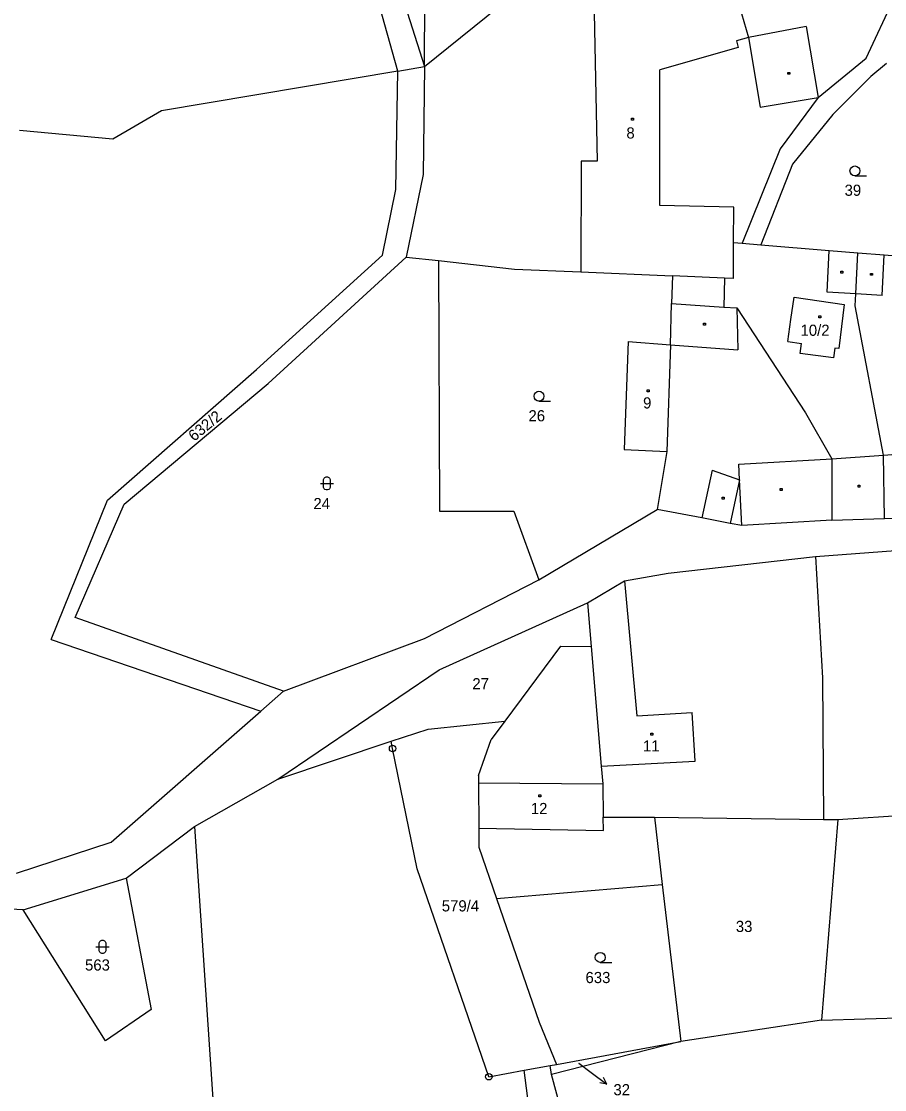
# Model space of a CAD drawing. Extents: x -794421 to -792735, y -1117671 to -1115559.
# Drawn here: x -793541.7 to -793410.2, y -1117055.3 to -1116892.5 of the extents above; entities that cross this region are included whole.
import ezdxf

# ---------------------------------------------------------------- set-up
doc = ezdxf.new("R2010")
doc.units = 0
for name, color, linetype in [('Komunikace', 7, 'Continuous'), ('Vrstva 1', 7, 'Continuous'), ('Vrstva 14', 7, 'Continuous'), ('Vrstva 15', 7, 'Continuous'), ('Vrstva 16', 7, 'Continuous'), ('Vrstva 2', 7, 'Continuous'), ('Vrstva 23', 7, 'Continuous'), ('Vrstva 25', 7, 'Continuous'), ('Vrstva 28', 7, 'Continuous')]:
    doc.layers.add(name, color=color, linetype=linetype)

msp = doc.modelspace()

# ---------------------------------------------------------------- linework, layer by layer
at = {"layer": 'Komunikace'}
msp.add_line((-793456.75, -1117051.29), (-793454.9, -1117052.67), dxfattribs=at)
at = {"layer": 'Vrstva 1'}
for p, q in [((-793484.35, -1116900.11), (-793495.76, -1116859.33)), ((-793493.13, -1116859), (-793480.31, -1116899.44)), ((-793412.98, -1116898.15), (-793406.34, -1116883.78)), ((-793433.75, -1116885.1), (-793430.93, -1116895.01)), ((-793480.31, -1116899.44), (-793464.48, -1116886.66)), ((-793480.31, -1116899.44), (-793480.23, -1116887.15)), ((-793454.44, -1116891.23), (-793454, -1116913.82)), ((-793422.11, -1116893.31), (-793430.93, -1116895.01)), ((-793422.11, -1116893.31), (-793420.28, -1116904.12)), ((-793420.28, -1116904.12), (-793412.98, -1116898.15)), ((-793484.35, -1116900.11), (-793520.39, -1116906.15)), ((-793484.67, -1116918.16), (-793484.35, -1116900.11)), ((-793484.35, -1116900.11), (-793480.31, -1116899.44)), ((-793480.31, -1116899.44), (-793480.48, -1116915.89)), ((-793409.89, -1116898.96), (-793412.29, -1116900.96)), ((-793412.29, -1116900.96), (-793418.05, -1116906.75)), ((-793420.28, -1116904.12), (-793426.11, -1116911.97)), ((-793520.39, -1116906.15), (-793527.81, -1116910.47)), ((-793418.05, -1116906.75), (-793424.23, -1116914.28)), ((-793527.81, -1116910.47), (-793542.02, -1116909.19)), ((-793426.11, -1116911.97), (-793431.88, -1116926.34)), ((-793456.41, -1116913.84), (-793456.46, -1116930.7)), ((-793454, -1116913.82), (-793456.41, -1116913.84)), ((-793424.23, -1116914.28), (-793429.04, -1116926.58)), ((-793480.48, -1116915.89), (-793483.08, -1116928.45)), ((-793486.7, -1116928.15), (-793484.67, -1116918.16)), ((-793433.23, -1116931.71), (-793433.2, -1116926.23)), ((-793433.2, -1116926.23), (-793431.88, -1116926.34)), ((-793431.88, -1116926.34), (-793429.04, -1116926.58)), ((-793429.04, -1116926.58), (-793418.62, -1116927.44)), ((-793418.62, -1116927.44), (-793414.25, -1116927.8)), ((-793414.56, -1116934.07), (-793414.25, -1116927.8)), ((-793414.25, -1116927.8), (-793410.24, -1116928.13)), ((-793505.9, -1116945.6), (-793486.7, -1116928.15)), ((-793504.14, -1116947.69), (-793483.08, -1116928.45)), ((-793483.08, -1116928.45), (-793478.18, -1116928.99)), ((-793478.18, -1116928.99), (-793478.01, -1116967.17)), ((-793478.18, -1116928.99), (-793466.59, -1116930.28)), ((-793410.24, -1116928.13), (-793404, -1116928.64)), ((-793466.59, -1116930.28), (-793456.46, -1116930.7)), ((-793456.46, -1116930.7), (-793442.51, -1116931.29)), ((-793442.51, -1116931.29), (-793442.63, -1116935.51)), ((-793434.57, -1116931.65), (-793442.51, -1116931.29)), ((-793434.57, -1116931.65), (-793434.69, -1116936.06)), ((-793433.23, -1116931.71), (-793434.57, -1116931.65)), ((-793414.65, -1116935.87), (-793414.56, -1116934.07)), ((-793442.82, -1116941.81), (-793442.63, -1116935.51)), ((-793434.69, -1116936.06), (-793432.71, -1116936.2)), ((-793410.35, -1116958.65), (-793414.65, -1116935.87)), ((-793432.71, -1116936.2), (-793422.24, -1116952.16)), ((-793449.26, -1116941.34), (-793449.88, -1116957.77)), ((-793449.26, -1116941.34), (-793442.82, -1116941.81)), ((-793528.62, -1116965.47), (-793505.9, -1116945.6)), ((-793526.04, -1116966.12), (-793504.14, -1116947.69)), ((-793422.24, -1116952.16), (-793418.23, -1116959.21)), ((-793449.88, -1116957.77), (-793443.37, -1116958.06)), ((-793443.37, -1116958.06), (-793444.86, -1116966.92)), ((-793410.19, -1116968.29), (-793410.35, -1116958.65)), ((-793418.23, -1116959.21), (-793418.24, -1116968.53)), ((-793537.18, -1116986.72), (-793528.62, -1116965.47)), ((-793533.55, -1116983.36), (-793526.04, -1116966.12)), ((-793462.86, -1116977.65), (-793444.86, -1116966.92)), ((-793438.02, -1116968.2), (-793444.86, -1116966.92)), ((-793478.01, -1116967.17), (-793466.67, -1116967.15)), ((-793466.67, -1116967.15), (-793462.86, -1116977.65)), ((-793433.69, -1116969.02), (-793438.02, -1116968.2)), ((-793418.24, -1116968.53), (-793431.92, -1116969.35)), ((-793418.24, -1116968.53), (-793410.19, -1116968.29)), ((-793410.19, -1116968.29), (-793402.09, -1116967.98)), ((-793431.92, -1116969.35), (-793433.69, -1116969.02)), ((-793420.73, -1116974.09), (-793391.73, -1116971.89)), ((-793443.14, -1116976.59), (-793420.73, -1116974.09)), ((-793420.73, -1116974.09), (-793419.65, -1116992.58)), ((-793449.81, -1116977.8), (-793443.14, -1116976.59)), ((-793480.3, -1116986.56), (-793462.86, -1116977.65)), ((-793455.46, -1116981.14), (-793449.81, -1116977.8)), ((-793478.04, -1116991.32), (-793455.46, -1116981.14)), ((-793455.46, -1116981.14), (-793454.9, -1116987.78)), ((-793501.76, -1116994.58), (-793533.55, -1116983.36)), ((-793501.76, -1116994.58), (-793480.3, -1116986.56)), ((-793537.18, -1116986.72), (-793505.25, -1116997.64)), ((-793459.56, -1116987.73), (-793468.07, -1116999.16)), ((-793459.56, -1116987.73), (-793454.9, -1116987.78)), ((-793454.9, -1116987.78), (-793453.36, -1117006.02)), ((-793502.66, -1117008.02), (-793478.04, -1116991.32)), ((-793419.65, -1116992.58), (-793419.5, -1117014.13)), ((-793505.25, -1116997.64), (-793501.76, -1116994.58)), ((-793528.06, -1117017.62), (-793505.25, -1116997.64)), ((-793479.72, -1117000.39), (-793468.07, -1116999.16)), ((-793468.07, -1116999.16), (-793470.15, -1117001.95)), ((-793485.38, -1117002.2), (-793479.72, -1117000.39)), ((-793502.66, -1117008.02), (-793485.38, -1117002.2)), ((-793485.15, -1117003.33), (-793485.38, -1117002.2)), ((-793472.08, -1117007.46), (-793470.15, -1117001.95)), ((-793481.39, -1117021.68), (-793485.15, -1117003.33)), ((-793453.36, -1117006.02), (-793453.13, -1117008.72)), ((-793472.08, -1117007.46), (-793472.08, -1117008.58)), ((-793515.34, -1117015.21), (-793502.66, -1117008.02)), ((-793472.08, -1117008.58), (-793472.03, -1117015.46)), ((-793453.13, -1117008.72), (-793453.06, -1117013.8)), ((-793417.29, -1117014.16), (-793391.93, -1117012.5)), ((-793453.06, -1117013.8), (-793445.23, -1117013.81)), ((-793445.23, -1117013.81), (-793444.1, -1117024.06)), ((-793445.23, -1117013.81), (-793419.5, -1117014.13)), ((-793417.29, -1117014.16), (-793419.8, -1117044.7)), ((-793419.5, -1117014.13), (-793417.29, -1117014.16)), ((-793525.73, -1117023.07), (-793515.34, -1117015.21)), ((-793515.34, -1117015.21), (-793508.73, -1117114.25)), ((-793472.03, -1117015.46), (-793472.01, -1117018.35)), ((-793542.45, -1117022.32), (-793528.06, -1117017.62)), ((-793472.01, -1117018.35), (-793469.31, -1117026.18)), ((-793470.5, -1117053.33), (-793481.39, -1117021.68)), ((-793541.43, -1117027.89), (-793525.73, -1117023.07)), ((-793525.73, -1117023.07), (-793521.97, -1117043.07)), ((-793469.31, -1117026.18), (-793444.1, -1117024.06)), ((-793444.1, -1117024.06), (-793441.22, -1117047.99)), ((-793541.43, -1117027.89), (-793556.14, -1117027.18)), ((-793469.31, -1117026.18), (-793462.81, -1117045.04)), ((-793528.89, -1117047.89), (-793541.43, -1117027.89)), ((-793521.97, -1117043.07), (-793528.89, -1117047.89)), ((-793462.81, -1117045.04), (-793460.19, -1117051.45)), ((-793419.8, -1117044.7), (-793441.22, -1117047.99)), ((-793419.8, -1117044.7), (-793387.04, -1117043.8)), ((-793441.22, -1117047.99), (-793460.94, -1117053)), ((-793460.19, -1117051.45), (-793441.22, -1117047.99)), ((-793465.13, -1117052.35), (-793461.14, -1117051.62)), ((-793461.14, -1117051.62), (-793460.19, -1117051.45)), ((-793460.94, -1117053), (-793461.14, -1117051.62)), ((-793470.5, -1117053.33), (-793465.13, -1117052.35)), ((-793463.93, -1117061.05), (-793465.13, -1117052.35)), ((-793451.13, -1117089.23), (-793460.94, -1117053))]:
    msp.add_line(p, q, dxfattribs=at)
at = {"layer": 'Vrstva 16'}
for p, q in [((-793454.9, -1117052.67), (-793452.495, -1117054.463)), ((-793452.495, -1117054.463), (-793453.595, -1117054.266)), ((-793452.495, -1117054.463), (-793452.997, -1117053.464))]:
    msp.add_line(p, q, dxfattribs=at)
at = {"layer": 'Vrstva 2'}
for p, q in [((-793430.93, -1116895.01), (-793432.77, -1116895.53)), ((-793430.93, -1116895.01), (-793429.12, -1116905.6)), ((-793432.49, -1116896.52), (-793444.45, -1116899.92)), ((-793432.77, -1116895.53), (-793432.49, -1116896.52)), ((-793444.45, -1116920.58), (-793444.45, -1116899.92)), ((-793429.12, -1116905.6), (-793420.28, -1116904.12)), ((-793433.18, -1116920.85), (-793444.45, -1116920.58)), ((-793433.2, -1116926.23), (-793433.18, -1116920.85)), ((-793418.94, -1116933.8), (-793418.62, -1116927.44)), ((-793410.54, -1116934.32), (-793410.24, -1116928.13)), ((-793414.56, -1116934.07), (-793418.94, -1116933.8)), ((-793410.54, -1116934.32), (-793414.56, -1116934.07)), ((-793442.63, -1116935.51), (-793434.69, -1116936.06)), ((-793424.47, -1116937.94), (-793423.98, -1116934.54)), ((-793423.98, -1116934.54), (-793416.35, -1116935.67)), ((-793416.35, -1116935.67), (-793417.15, -1116942.4)), ((-793432.71, -1116936.2), (-793432.56, -1116942.56)), ((-793424.95, -1116941.33), (-793424.47, -1116937.94)), ((-793442.82, -1116941.81), (-793443.37, -1116958.06)), ((-793442.82, -1116941.81), (-793432.56, -1116942.56)), ((-793424.95, -1116941.33), (-793422.84, -1116941.62)), ((-793423.06, -1116943.12), (-793422.84, -1116941.62)), ((-793417.75, -1116942.32), (-793417.96, -1116943.82)), ((-793417.15, -1116942.4), (-793417.75, -1116942.32)), ((-793417.96, -1116943.82), (-793423.06, -1116943.12)), ((-793418.23, -1116959.21), (-793410.35, -1116958.65)), ((-793410.35, -1116958.65), (-793402.5, -1116958.04)), ((-793432.41, -1116960.02), (-793418.23, -1116959.21)), ((-793432.29, -1116962.37), (-793432.41, -1116960.02)), ((-793436.48, -1116960.91), (-793438.02, -1116968.2)), ((-793436.48, -1116960.91), (-793432.29, -1116962.37)), ((-793432.29, -1116962.37), (-793433.69, -1116969.02)), ((-793431.92, -1116969.35), (-793432.29, -1116962.37)), ((-793449.81, -1116977.8), (-793447.92, -1116998.36)), ((-793447.92, -1116998.36), (-793439.51, -1116997.85)), ((-793439.05, -1117005.24), (-793439.51, -1116997.85)), ((-793453.36, -1117006.02), (-793439.05, -1117005.24)), ((-793472.08, -1117008.58), (-793453.13, -1117008.72)), ((-793453.04, -1117015.84), (-793453.06, -1117013.8)), ((-793472.03, -1117015.46), (-793453.04, -1117015.84))]:
    msp.add_line(p, q, dxfattribs=at)
at = {"layer": 'Vrstva 23'}
for p, q in [((-793414.71, -1116916.07), (-793412.96, -1116916.07)), ((-793462.85, -1116950.4), (-793461.1, -1116950.4)), ((-793495.66, -1116962.34), (-793495.56, -1116962.14)), ((-793495.56, -1116962.14), (-793495.46, -1116962.04)), ((-793495.46, -1116962.04), (-793495.26, -1116961.94)), ((-793495.26, -1116961.94), (-793495.06, -1116961.94)), ((-793495.06, -1116961.94), (-793494.86, -1116962.04)), ((-793494.86, -1116962.04), (-793494.76, -1116962.14)), ((-793494.76, -1116962.14), (-793494.66, -1116962.34)), ((-793496.16, -1116962.94), (-793494.16, -1116962.94)), ((-793495.66, -1116963.54), (-793495.66, -1116962.34)), ((-793495.56, -1116963.74), (-793495.66, -1116963.54)), ((-793495.46, -1116963.84), (-793495.56, -1116963.74)), ((-793494.76, -1116963.74), (-793494.86, -1116963.84)), ((-793494.66, -1116963.54), (-793494.76, -1116963.74)), ((-793494.66, -1116962.34), (-793494.66, -1116963.54)), ((-793495.26, -1116963.94), (-793495.46, -1116963.84)), ((-793495.06, -1116963.94), (-793495.26, -1116963.94)), ((-793494.86, -1116963.84), (-793495.06, -1116963.94)), ((-793530.36, -1117033.54), (-793528.36, -1117033.54)), ((-793529.86, -1117032.94), (-793529.76, -1117032.74)), ((-793529.86, -1117034.14), (-793529.86, -1117032.94)), ((-793529.76, -1117032.74), (-793529.66, -1117032.64)), ((-793529.66, -1117032.64), (-793529.46, -1117032.54)), ((-793529.46, -1117032.54), (-793529.26, -1117032.54)), ((-793529.26, -1117032.54), (-793529.06, -1117032.64)), ((-793529.06, -1117032.64), (-793528.96, -1117032.74)), ((-793528.96, -1117032.74), (-793528.86, -1117032.94)), ((-793528.86, -1117032.94), (-793528.86, -1117034.14)), ((-793529.76, -1117034.34), (-793529.86, -1117034.14)), ((-793529.66, -1117034.44), (-793529.76, -1117034.34)), ((-793529.46, -1117034.54), (-793529.66, -1117034.44)), ((-793529.26, -1117034.54), (-793529.46, -1117034.54)), ((-793529.06, -1117034.44), (-793529.26, -1117034.54)), ((-793528.96, -1117034.34), (-793529.06, -1117034.44)), ((-793528.86, -1117034.14), (-793528.96, -1117034.34)), ((-793453.52, -1117035.91), (-793451.77, -1117035.91))]:
    msp.add_line(p, q, dxfattribs=at)
for centre in [(-793414.71, -1116915.32), (-793462.85, -1116949.65), (-793453.52, -1117035.16)]:
    msp.add_circle(centre, 0.75, dxfattribs=at)
at = {"layer": 'Vrstva 25'}
for p, q in [((-793424.93, -1116900.31), (-793424.63, -1116900.31)), ((-793424.93, -1116900.61), (-793424.93, -1116900.31)), ((-793424.63, -1116900.31), (-793424.63, -1116900.61)), ((-793424.63, -1116900.61), (-793424.93, -1116900.61)), ((-793448.73, -1116907.27), (-793448.43, -1116907.27)), ((-793448.73, -1116907.57), (-793448.73, -1116907.27)), ((-793448.43, -1116907.57), (-793448.73, -1116907.57)), ((-793448.43, -1116907.27), (-793448.43, -1116907.57)), ((-793416.87, -1116930.61), (-793416.57, -1116930.61)), ((-793416.87, -1116930.91), (-793416.87, -1116930.61)), ((-793416.57, -1116930.91), (-793416.87, -1116930.91)), ((-793416.57, -1116930.61), (-793416.57, -1116930.91)), ((-793412.32, -1116930.93), (-793412.02, -1116930.93)), ((-793412.32, -1116931.23), (-793412.32, -1116930.93)), ((-793412.02, -1116931.23), (-793412.32, -1116931.23)), ((-793412.02, -1116930.93), (-793412.02, -1116931.23)), ((-793420.22, -1116937.43), (-793419.92, -1116937.43)), ((-793420.22, -1116937.73), (-793420.22, -1116937.43)), ((-793419.92, -1116937.73), (-793420.22, -1116937.73)), ((-793419.92, -1116937.43), (-793419.92, -1116937.73)), ((-793437.79, -1116938.54), (-793437.49, -1116938.54)), ((-793437.79, -1116938.84), (-793437.79, -1116938.54)), ((-793437.49, -1116938.84), (-793437.79, -1116938.84)), ((-793437.49, -1116938.54), (-793437.49, -1116938.84)), ((-793446.37, -1116948.7), (-793446.07, -1116948.7)), ((-793446.37, -1116949), (-793446.37, -1116948.7)), ((-793446.07, -1116949), (-793446.37, -1116949)), ((-793446.07, -1116948.7), (-793446.07, -1116949)), ((-793426.07, -1116963.73), (-793425.77, -1116963.73)), ((-793426.07, -1116964.03), (-793426.07, -1116963.73)), ((-793425.77, -1116963.73), (-793425.77, -1116964.03)), ((-793414.23, -1116963.23), (-793413.93, -1116963.23)), ((-793414.23, -1116963.53), (-793414.23, -1116963.23)), ((-793413.93, -1116963.53), (-793414.23, -1116963.53)), ((-793413.93, -1116963.23), (-793413.93, -1116963.53)), ((-793434.93, -1116965.02), (-793434.63, -1116965.02)), ((-793434.93, -1116965.32), (-793434.93, -1116965.02)), ((-793434.63, -1116965.32), (-793434.93, -1116965.32)), ((-793434.63, -1116965.02), (-793434.63, -1116965.32)), ((-793425.77, -1116964.03), (-793426.07, -1116964.03)), ((-793445.79, -1117001), (-793445.49, -1117001)), ((-793445.79, -1117001.3), (-793445.79, -1117001)), ((-793445.49, -1117001), (-793445.49, -1117001.3)), ((-793445.49, -1117001.3), (-793445.79, -1117001.3)), ((-793462.87, -1117010.4), (-793462.57, -1117010.4)), ((-793462.87, -1117010.7), (-793462.87, -1117010.4)), ((-793462.57, -1117010.7), (-793462.87, -1117010.7)), ((-793462.57, -1117010.4), (-793462.57, -1117010.7))]:
    msp.add_line(p, q, dxfattribs=at)
at = {"layer": 'Vrstva 28'}
for centre, radius in [((-793485.15, -1117003.33), 0.5), ((-793485.15, -1117003.33), 0.01), ((-793470.5, -1117053.33), 0.5), ((-793470.5, -1117053.33), 0.01)]:
    msp.add_circle(centre, radius, dxfattribs=at)

# ---------------------------------------------------------------- texts
at = {"layer": 'Vrstva 14'}
for s, height, p in [('39', 1.7, (-793416.277, -1116919.12)), ('26', 1.7, (-793464.447, -1116953.48)), ('24', 1.7, (-793497.222, -1116966.86)), ('27', 1.7, (-793473.003, -1116994.31)), ('579/4', 1.7, (-793477.659, -1117028.15)), ('33', 1.7, (-793432.847, -1117031.28)), ('563', 1.7, (-793532.023, -1117037.16)), ('633', 1.7, (-793455.757, -1117039.07)), ('32', 0.1, (-793456.835, -1117051.29))]:
    msp.add_text(s, height=height, dxfattribs=at).set_placement(p)
msp.add_text('632/2', height=1.7, rotation=39.47886, dxfattribs=at).set_placement((-793515.403, -1116956.619))
at = {"layer": 'Vrstva 15'}
for s, p in [('8', (-793449.527, -1116910.39)), ('10/2', (-793422.992, -1116940.45)), ('9', (-793446.987, -1116951.52)), ('11', (-793446.993, -1117003.78)), ('12', (-793464.09, -1117013.32))]:
    msp.add_text(s, height=1.7, dxfattribs=at).set_placement(p)
at = {"layer": 'Vrstva 16'}
msp.add_text('32', height=1.7, dxfattribs=at).set_placement((-793451.5, -1117056.16))

doc.saveas('drawing.dxf')
